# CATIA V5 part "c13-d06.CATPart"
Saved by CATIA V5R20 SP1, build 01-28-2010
Part number: Part1
Bounding box of the stored display mesh (mm): x -40 to 40, y -65 to 65, z 0 to 15
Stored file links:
  D:\v5_r20\psrt_files_downloaded\c13-catia-v5r20-prt\Figure 13-19\c13-d06.CATPart
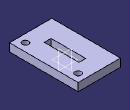
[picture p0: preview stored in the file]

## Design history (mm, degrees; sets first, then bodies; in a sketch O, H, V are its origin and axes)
Body1 (main body)
  Sketch1 on xy-plane, origin (0, 0, 0), H (1, 0, 0), V (0, 1, 0)
    line L1 (40, 65) -> (40, -65)
    line L2 (40, -65) -> (-40, -65)
    line L3 (-40, -65) -> (-40, 65)
    line L4 (-40, 65) -> (40, 65)
    length L1 = 130
    length L2 = 80
    vertical: L1 V, L3 V
    horizontal: L2 H, L4 H
    equidistance: L1 L3 O, L2 L4 O
  Pad1: profile Sketch1, direction (0, 0, 1), length 15
  Sketch2 on face of Pad1, origin (0, 0, 15), H (1, 0, 0), V (0, 1, 0)
    line L1 (6.4019, 32.7538) -> (6.4019, -32.7538)
    line L2 (6.4019, -32.7538) -> (-6.4019, -32.7538)
    line L3 (-6.4019, -32.7538) -> (-6.4019, 32.7538)
    line L4 (-6.4019, 32.7538) -> (6.4019, 32.7538)
    vertical: L1 V, L3 V
    horizontal: L2 H, L4 H
    equidistance: L1 L3 O, L2 L4 O
  Pocket1: profile Sketch2, direction (0, 0, -1), through (limit type 3)
  Sketch3 on face of Pad1, origin (30.5043, -33.5377, 15), H (1, 0, 0), V (0, 1, 0)
    point P1 (-5.5043, -16.4623)
    reference projected line E1 (9.4957, -31.4623) -> (9.4957, 98.5377) from edge [face of Pad1 | face of Pad1]
    reference projected line E2 (-70.5043, -31.4623) -> (9.4957, -31.4623) from edge [face of Pad1 | face of Pad1]
    distance P1 E1 = 15
    distance P1 E2 = 15
  Hole1: placed by Sketch3, at (25, -50, 15) direction (0, 0, -1), diameter 12, through (limit type 3)
  Mirror1: of Hole1, about zx-plane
